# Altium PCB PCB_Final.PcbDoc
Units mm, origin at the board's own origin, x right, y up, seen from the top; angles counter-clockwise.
Board outline 33.1 x 39.88 mm, 2 copper layers (Top Layer, Bottom Layer); 74 components, 65 nets, 291 pads, 28 vias.
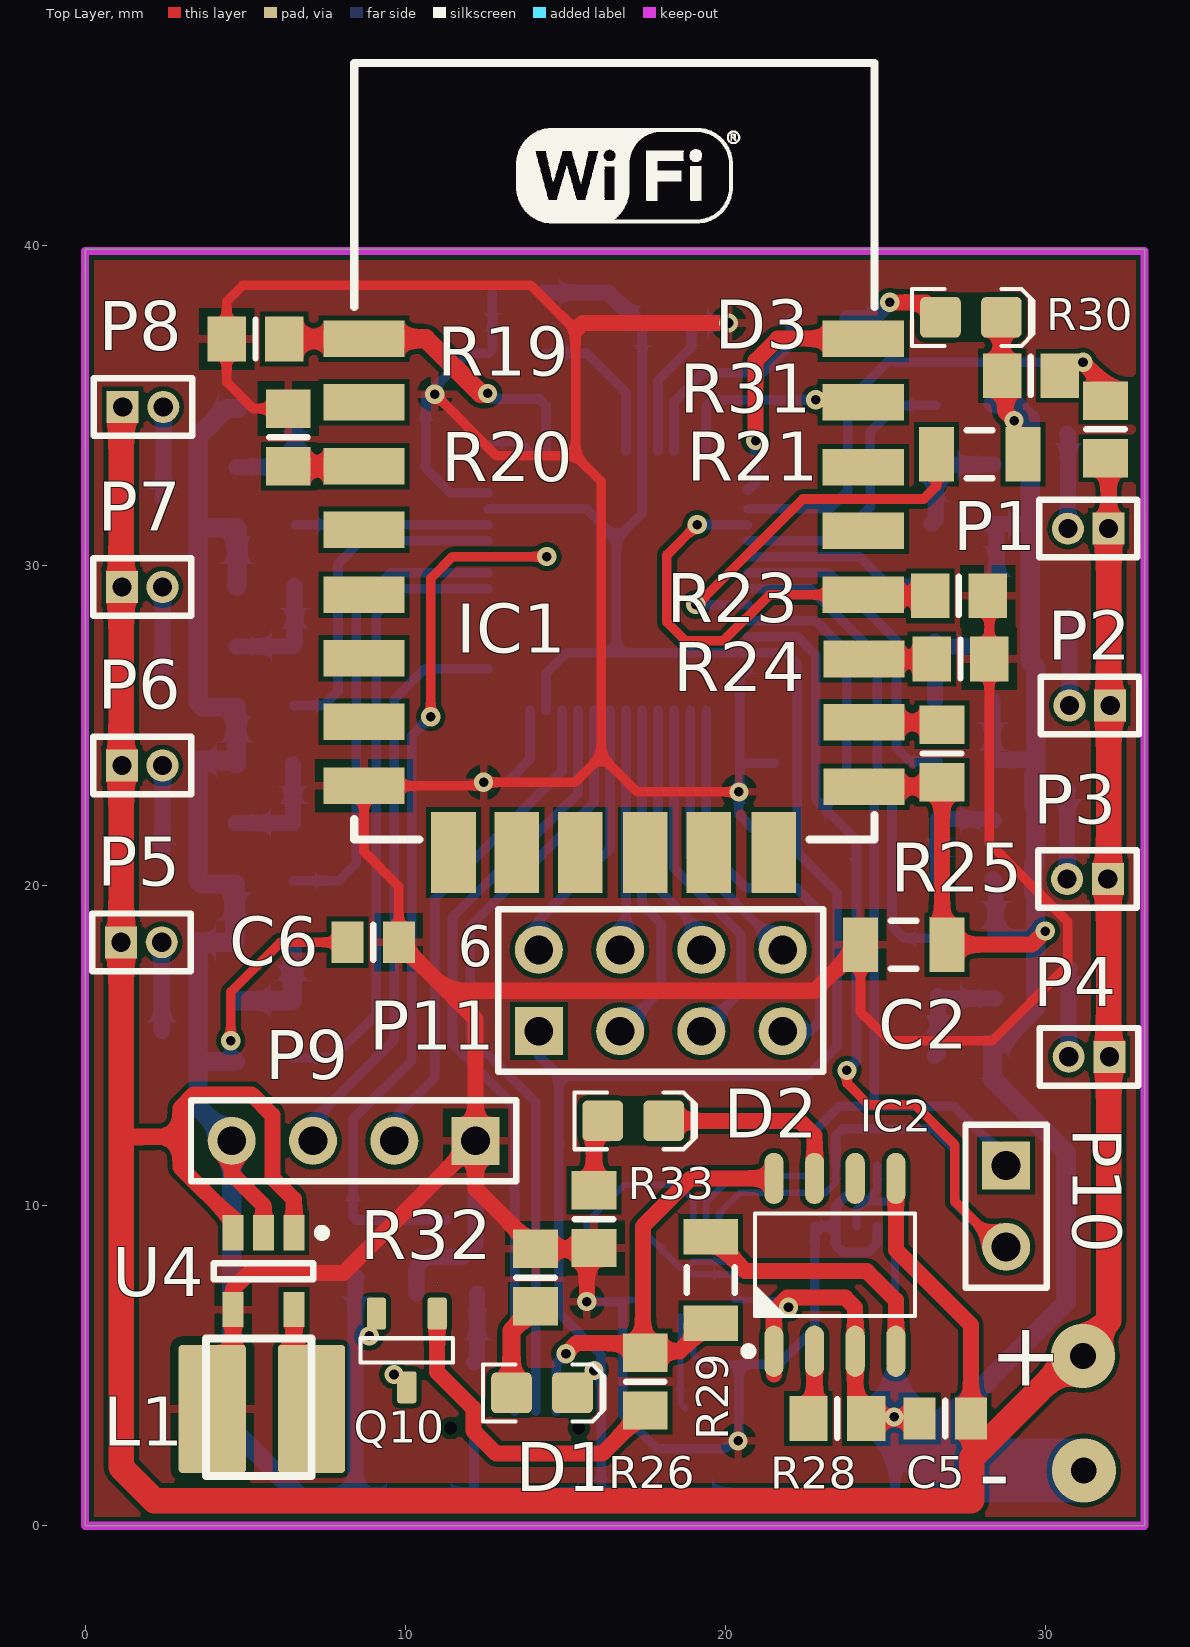
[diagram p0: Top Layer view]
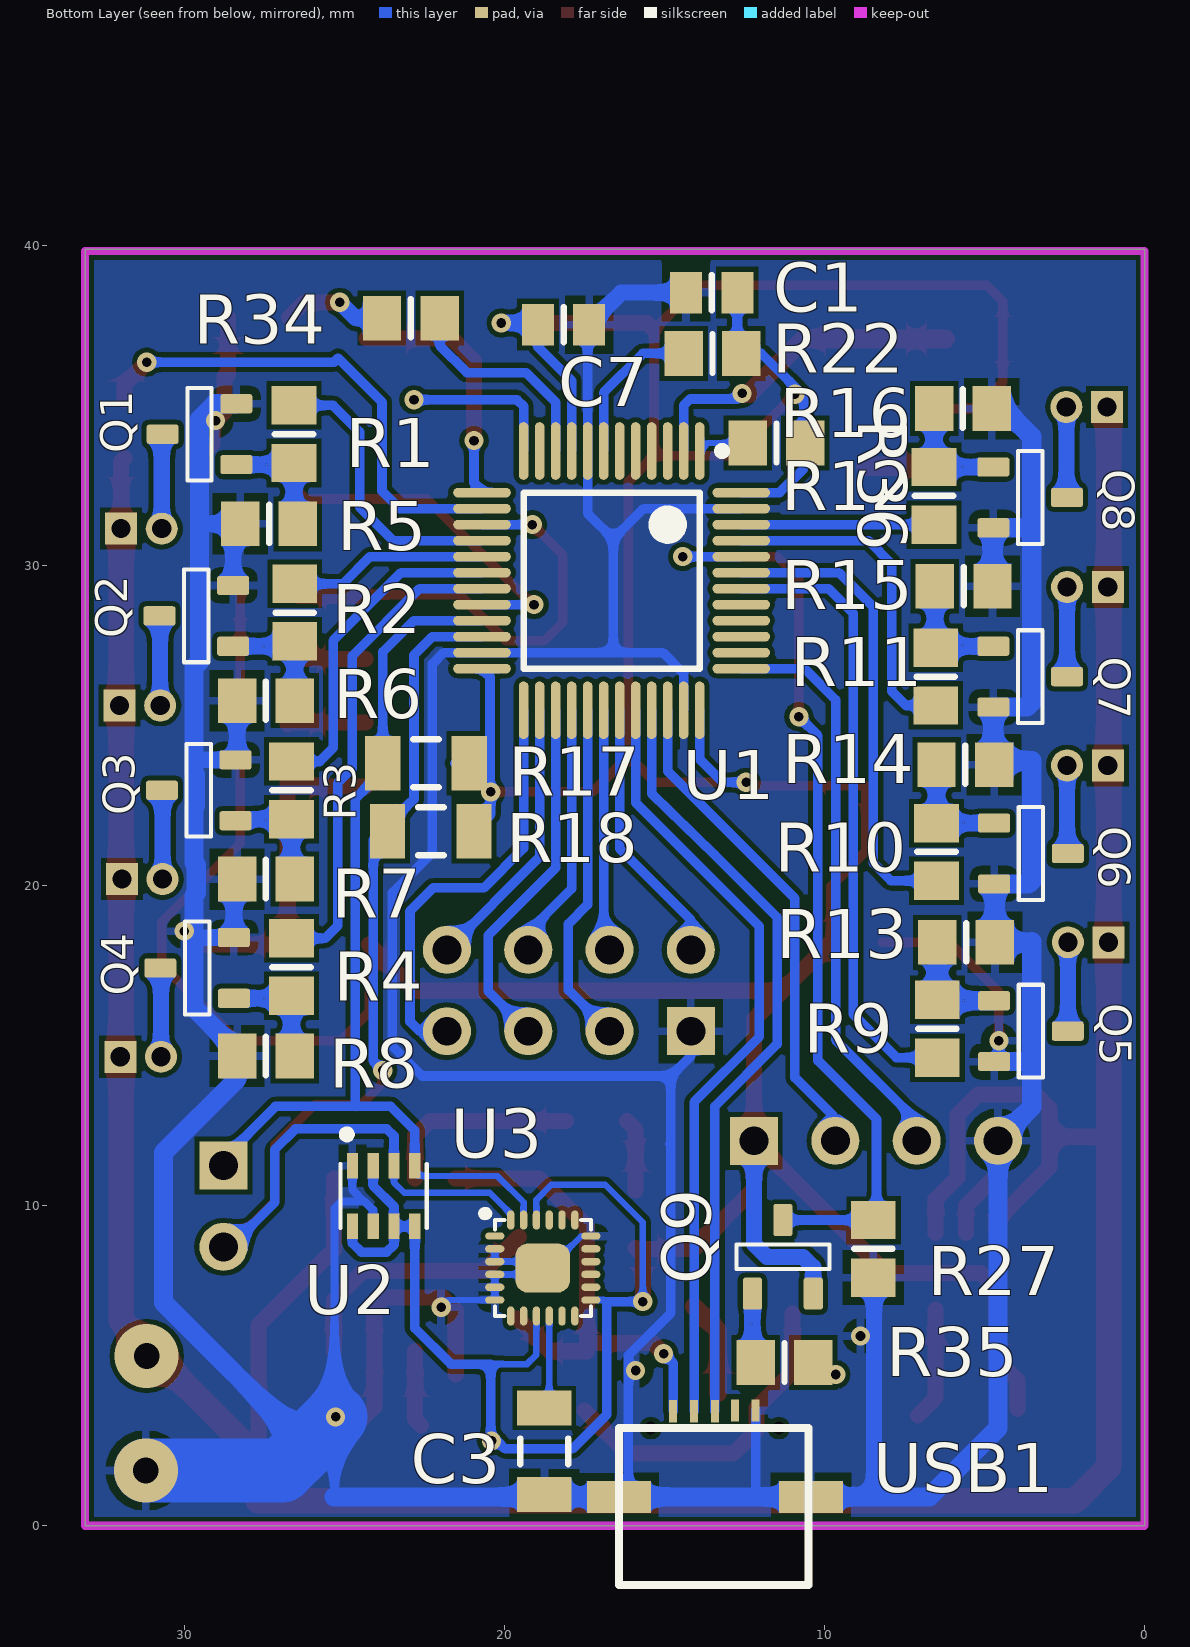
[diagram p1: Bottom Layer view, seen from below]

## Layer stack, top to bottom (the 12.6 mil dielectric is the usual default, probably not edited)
Top Solder: solder mask 0.0102, Solder Resist, Dk 3.5
Top Layer: signal copper 0.0356
Dielectric 1: dielectric 0.32, FR-4, Dk 4.8
Bottom Layer: signal copper 0.0356
Bottom Solder: solder mask 0.0102, Solder Resist, Dk 3.5

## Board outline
0,0 33.1,0 33.1,39.875 0,39.875

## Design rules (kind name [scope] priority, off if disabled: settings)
Clearance [All] p1: gap=0.15
PolygonConnect [All] p1: connectstyle=Relief reliefconductorwidth=0.254 reliefentries=4 polygonreliefangle="90 Angle" airgapwidth=0.254
RoutingVias [All] p1: holewidth=0.711 width=1.27 viastyle="Through Hole" minholewidth=0.711 minwidth=1.27 maxholewidth=0.711 maxwidth=1.27
SolderMaskExpansion [All] p1: expansion=0.102
Width [All] p1: maxlimit=2 minlimit=0.2 preferedwidth=0.5
30 further rules are at their usual default settings.

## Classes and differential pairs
component class Potencia: C5 C6 C7 C? D1 D2 D3 IC2 L1 P1 P2 P3 P4 P5 P6 P7 P8 P? Q1 Q2 Q3 Q4 Q5 Q6 Q7 Q8 Q? R1 R2 R3 R4 R5 R6 R7 R8 R9 R10 R11 R12 R13 R14 R15 R16 R28 R29 R32 R33 R34 R? U4
component class Esquematico: C1 C2 C3 C? IC1 P9 P10 P11 Q9 Q10 R17 R18 R19 R20 R21 R22 R23 R24 R25 R26 R27 R30 R31 R35 R36 R? U1 U2 U3 U? USB1

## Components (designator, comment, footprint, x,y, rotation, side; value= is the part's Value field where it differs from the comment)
C1 "Cap" 6-0805_L 13.525,38.525 r180 bottom
C2 "Cap" C1206 25.575,18.15 r180 top
C3 "Cap" C1206 18.75,2.325 r90 bottom
C5 "Cap" 6-0805_L 26.875,3.35 r0 top
C6 "Cap" 6-0805_L 9,18.225 r0 top
C7 "Cap" 6-0805_L 18.15,37.525 r0 bottom
D1 "Diode" LED-0805 14.275,4.15 r0 top
D2 "Diode" LED-0805 17.125,12.65 r0 top
D3 "Diode" LED-0805 27.675,37.75 r0 top
IC1 "ESP8266 ESP-12-E" "ESP8266 ESP-12-E B" 25.3,20.675 r0 top
IC2 "TP4056" SOIC127P600X175-8AN 23.425,8.15 r90 top
L1 "Inductor Iron Dot" "Inductor CD43" 8.075,1.65 r90 top
P1 "MHDR1X2" MHDR1X2 31.975,31.15 r180 top
P2 "MHDR1X2" MHDR1X2 32.025,25.625 r180 top
P3 "MHDR1X2" MHDR1X2 31.95,20.2 r180 top
P4 "MHDR1X2" MHDR1X2 32,14.65 r180 top
P5 "MHDR1X2" MHDR1X2 1.125,18.225 r0 top
P6 "MHDR1X2" MHDR1X2 1.15,23.75 r0 top
P7 "MHDR1X2" MHDR1X2 1.15,29.325 r0 top
P8 "MHDR1X2" MHDR1X2 1.175,34.95 r0 top
P9 "Header 4" HDR1X4 12.2,12.025 r180 top
P10 "Header 2" HDR1X2 28.775,11.25 r270 top
P11 "Header 4X2A" HDR2X4_CEN 14.175,15.45 r0 top
Q1 "AO3406" SOT23-3 29.525,34.1 r0 bottom
Q2 "AO3406" SOT23-3 29.625,28.425 r0 bottom
Q3 "AO3406" SOT23-3 29.55,22.975 r0 bottom
Q4 "AO3406" SOT23-3 29.6,17.425 r0 bottom
Q5 "AO3406" SOT23-3 3.55,15.45 r180 bottom
Q6 "AO3406" SOT23-3 3.55,21 r180 bottom
Q7 "AO3406" SOT23-3 3.575,26.525 r180 bottom
Q8 "AO3406" SOT23-3 3.575,32.125 r180 bottom
Q9 "S8055" SOT23-3 11.3,8.4 r90 bottom
Q10 "S8050" SOT23-3 10.05,5.475 r270 top
R1 "Res3" 6-0805_N 26.575,34.1 r90 bottom
R2 "Res3" 6-0805_N 26.55,28.525 r90 bottom
R3 "Res3" 6-0805_N 26.65,22.975 r90 bottom
R4 "Res3" 6-0805_N 26.65,17.45 r90 bottom
R5 "Res3" 6-0805_N 27.35,31.3 r180 bottom
R6 "Res3" 6-0805_N 27.45,25.775 r180 bottom
R7 "Res3" 6-0805_N 27.45,20.2 r180 bottom
R8 "Res3" 6-0805_N 27.45,14.675 r180 bottom
R9 "Res3" 6-0805_N 6.475,15.525 r270 bottom
R10 "Res3" 6-0805_N 6.5,21.05 r270 bottom
R11 "Res3" 6-0805_N 6.525,26.525 r270 bottom
R12 "Res3" 6-0805_N 6.575,32.175 r270 bottom
R13 "Res3" 6-0805_N 5.575,18.225 r0 bottom
R14 "Res3" 6-0805_N 5.6,23.775 r0 bottom
R15 "Res3" 6-0805_N 5.65,29.35 r0 bottom
R16 "Res3" 6-0805_N 5.675,34.9 r0 bottom
R17 "Res3" C1206 22.45,23.825 r0 bottom
R18 "Res3" C1206 22.3,21.7 r0 bottom
R19 "Res3" 6-0805_N 5.325,37.075 r180 top
R20 "Res3" 6-0805_N 6.35,34 r90 top
R21 "Res3" C1206 27.95,33.475 r0 top
R22 "Res3" 6-0805_N 13.5,36.625 r180 bottom
R23 "Res3" 6-0805_N 27.3,29.05 r0 top
R24 "Res3" 6-0805_N 27.35,27.075 r180 top
R25 "Res3" 6-0805_N 26.775,24.125 r90 top
R26 "Res3" 6-0805_N 17.5,4.5 r270 top
R27 "Res3" 6-0805_N 8.475,8.65 r270 bottom
R28 "Res3" 6-0805_N 23.5,3.35 r0 top
R29 "Res3" C1206 19.55,7.675 r90 top
R30 "Res3" 6-0805_N 31.875,34.25 r90 top
R31 "Res3" 6-0805_N 29.55,35.925 r180 top
R32 "Res3" 6-0805_N 14.075,7.75 r90 top
R33 "Res3" 6-0805_N 15.9,9.575 r270 top
R34 "Res3" 6-0805_N 22.925,37.725 r180 bottom
R35 "Res3" 6-0805_N 11.25,5.1 r180 bottom
R36 "Res3" 6-0805_N 11.5,33.825 r180 bottom
U1 "STM32F103C8T6" LQFP48_N 16.65,29.525 r270 bottom
U2 "BMP280" LGA-8_BMP280(Primary) 23.775,10.3 r90 bottom
U3 "GYRO/ACCEL/COMPASS/9-AXIS" QFN-24/3MM 18.8,8.05 r180 bottom
U4 "LM3671MF-3.3/NOPB" MF05A_N 5.575,7.95 r270 top
USB1 "Micro_USB" "Micro USB" 15.425,3.05 r180 bottom

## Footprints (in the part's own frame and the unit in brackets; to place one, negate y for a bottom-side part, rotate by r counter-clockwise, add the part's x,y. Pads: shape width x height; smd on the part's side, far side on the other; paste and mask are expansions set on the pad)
6-0805_L [mm] "Chip Resistor, Body 2.0x1.2mm, IPC High Density"
  rect 1x1.3 smd: 1(-0.8,0) 2(0.8,0)
  silkscreen extent 0,-0.55 0,0.55, body extent -1.07,-0.7 1.07,0.7, height 0.7
6-0805_N [mm] "Chip Resistor, Body 2.0x1.2mm, IPC Medium Density"
  rect 1.2x1.4 smd: 1(-0.9,0) 2(0.9,0)
  silkscreen extent 0,-0.6 0,0.6, body extent -1.07,-0.7 1.07,0.7, height 0.7
C1206 [mm] "Chip Capacitor, Body 3.2x1.6mm, IPC High Density"
  rect 1.1x1.7 smd: 1(-1.35,0) 2(1.35,0)
  silkscreen extent -0.4,-0.75 0.4,0.75, body extent -1.7,-0.9 1.7,0.9, height 1.3
"ESP8266 ESP-12-E B" [mil] "ESP8266 ESP-12-E"
  rect 100x45 smd: 1(-653,646) 2(-653,568) 3(-653,489) 4(-653,411) 5(-653,331) 6(-653,253) 7(-653,175) 8(-653,96) 15(-38,95) 16(-38,174) 17(-38,252) 18(-39,331) 19(-39,410) 20(-39,488) 21(-39,568) 22(-39,646)
  rect 55x100 smd: 9(-543,14) 10(-465,14) 11(-387,14) 12(-307,14) 13(-229,14) 14(-149,14)
  silkscreen extent -665,30 -25,985
HDR1X2 [mm] "Connector; Header; 2 Position"
  rect 1.5x1.5 hole 0.9: 1(0,0)
  round 1.5 hole 0.9: 2(2.54,0)
  silkscreen extent -1.27,-1.27 3.81,1.27
HDR1X4 [mm] "Connector; Header; 4 Position"
  rect 1.5x1.5 hole 0.9: 1(0,0)
  round 1.5 hole 0.9: 2(2.54,0) 3(5.08,0) 4(7.62,0)
  silkscreen extent -1.27,-1.27 8.89,1.27
HDR2X4_CEN [mm] "Connector; Header; 4x2 Position"
  rect 1.5x1.5 hole 0.9: 1(0,0)
  round 1.5 hole 0.9: 2(2.54,0) 3(5.08,0) 4(7.62,0) 5(0,2.54) 6(2.54,2.54) 7(5.08,2.54) 8(7.62,2.54)
  silkscreen extent -1.27,-1.27 8.89,3.81
"Inductor CD43" [mm] "4.5mm * 4mm"
  rrect10% 4x2.1 smd: 1(2,1) 2(2,4.1)
  silkscreen extent -0.1,1 4.2,4.3
LED-0805 [mil]
  round 20 on Mech15: 0(0,0)
  rrect25% 50x50 smd: 1(-37.5,0) 2(37.5,0)
  Top Layer pour cut-out: -15,30 15,30 15,-30 -15,-30
  silkscreen extent -72,-35 77,35, body extent -39,-25 39,25, height 31
LGA-8_BMP280(Primary) [mm]
  rect 0.8x0.35 smd paste-25.4 mask-25.4: 1(0.95,0.975) 2(0.95,0.325) 3(0.95,-0.325) 4(0.95,-0.975) 5(-0.95,-0.975) 6(-0.95,-0.325) 7(-0.95,0.325) 8(-0.95,0.975)
  silkscreen extent -1,-1.35 2.02,1.35
LQFP48_N [mm] "Thin QFP, 48-Leads, Body 7x7mm, Pitch 0.5mm, IPC Medium Density"
  oval 1.8x0.3 smd: 1(-4.05,2.75) 2(-4.05,2.25) 3(-4.05,1.75) 4(-4.05,1.25) 5(-4.05,0.75) 6(-4.05,0.25) 7(-4.05,-0.25) 8(-4.05,-0.75) 9(-4.05,-1.25) 10(-4.05,-1.75) 11(-4.05,-2.25) 12(-4.05,-2.75) 25(4.05,-2.75) 26(4.05,-2.25) 27(4.05,-1.75) 28(4.05,-1.25) 29(4.05,-0.75) 30(4.05,-0.25) 31(4.05,0.25) 32(4.05,0.75) 33(4.05,1.25) 34(4.05,1.75) 35(4.05,2.25) 36(4.05,2.75)
  oval 0.3x1.8 smd: 13(-2.75,-4.05) 14(-2.25,-4.05) 15(-1.75,-4.05) 16(-1.25,-4.05) 17(-0.75,-4.05) 18(-0.25,-4.05) 19(0.25,-4.05) 20(0.75,-4.05) 21(1.25,-4.05) 22(1.75,-4.05) 23(2.25,-4.05) 24(2.75,-4.05) 37(2.75,4.05) 38(2.25,4.05) 39(1.75,4.05) 40(1.25,4.05) 41(0.75,4.05) 42(0.25,4.05) 43(-0.25,4.05) 44(-0.75,4.05) 45(-1.25,4.05) 46(-1.75,4.05) 47(-2.25,4.05) 48(-2.75,4.05)
  silkscreen extent -4.17,-2.75 2.75,3.57, body extent -3.5,-3.5 3.5,3.5, height 1.6
MF05A_N [mm] "SOT23, 5-Leads, Body 2.9x1.6mm, Pitch 0.95mm, Lead Span 2.8mm, IPC Medium Density"
  rect 1.1x0.65 smd: 1(-1.2,0.95) 2(-1.2,0) 3(-1.2,-0.95) 4(1.2,-0.95) 5(1.2,0.95)
  silkscreen extent -1.32,-1.55 0.25,1.95, body extent -0.9,-1.55 0.9,1.55, height 1.19
MHDR1X2 [mm] "Connector; Header; 2 Position"
  rect 1x1 hole 0.6: 1(0,0)
  round 1 hole 0.6: 2(1.27,0)
  silkscreen extent -0.9,-0.9 2.17,0.9
"Micro USB" [mm]
  round 0 hole 0.4: 0(0,0) 0(4,0)
  rect 0.25x0.7 smd: 1(0.7,0.525) 2(1.35,0.525) 3(2,0.525) 4(2.625,0.55) 5(3.275,0.55)
  rect 2x1 smd: 6(-1,-2.15) 6(5,-2.15)
  silkscreen extent -1,-4.9 4.92,0
QFN-24/3MM [mm]
  rrect50% 1.7x1.54 smd: 0(0,0)
  rrect100% 0.6x0.23 smd: 1(-1.5,1) 2(-1.5,0.6) 3(-1.5,0.2) 4(-1.5,-0.2) 5(-1.5,-0.6) 6(-1.5,-1) 13(1.5,-1) 14(1.5,-0.6) 15(1.5,-0.2) 16(1.5,0.2) 17(1.5,0.6) 18(1.5,1)
  rrect100% 0.23x0.6 smd: 7(-1,-1.5) 8(-0.6,-1.5) 9(-0.2,-1.5) 10(0.2,-1.5) 11(0.6,-1.5) 12(1,-1.5) 19(1,1.5) 20(0.6,1.5) 21(0.2,1.5) 22(-0.2,1.5) 23(-0.6,1.5) 24(-1,1.5)
  silkscreen extent -2,-1.5 1.5,1.9
SOIC127P600X175-8AN [mm] "SOIC, 8-Leads, Body 4.9x3.9mm, Pitch 1.27mm, IPC Medium Density"
  round 1 on Mech15: 0(0,0)
  oval 1.6x0.6 smd: 1(-2.7,1.905) 2(-2.7,0.635) 3(-2.7,-0.635) 4(-2.7,-1.905) 5(2.7,-1.905) 6(2.7,-0.635) 7(2.7,0.635) 8(2.7,1.905)
  silkscreen extent -2.82,-2.5 1.6,2.82, body extent -3,-2.45 3,2.45, height 1.75
SOT23-3 [mm] "SOT23, 3 pin"
  round 0.5 on Mech15: 0(0,0)
  rrect25% 1x0.6 smd: 1(-1.15,0.95) 2(-1.15,-0.95) 3(1.15,0)
  silkscreen extent -0.38,-1.45 0.38,1.45, body extent -1.4,-1.45 1.4,1.45, height 1.29

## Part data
C1 C2 C3 C5 C6 C7: "Capacitor"
D1 D2 D3: "Default Diode"
L1: "Magnetic-Core Inductor with Winding Polarity Marking"
P1 P2 P3 P4 P5 P6 P7 P8 P10: "Header, 2-Pin"
P9: "Header, 4-Pin"
P11: "Header, 4-Pin, Dual row"
Q1 Q2 Q3 Q4 Q5 Q6 Q7 Q8: library part MOSFET-N, "N-Channel MOSFET"
Q9: "PNP SMD General Purpose Amplifier"
Q10: "NPN SMD General Purpose Amplifier"
R1 R2 R3 R4 R5 R6 R7 R8 R9 R10 R11 R12 R13 R14 R15 R16 R17 R18 R19 R20 R21 R22 R23 R24 R25 R26 R27 R28 R29 R30 R31 R32 R33 R34 R35 R36: "Resistor"
U1: "STM32 ARM-based 32-bit MCU with 64 Kbytes Flash, 48-pin LQFP, Industrial Temperature"
U2: "Barometro"
U3: library part MPU-9250
U4: "2MHz, 600mA Step-Down DC-DC Converter, 5-pin SOT-23, Pb-Free"

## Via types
v1: diameter 0.6, hole 0.3, Top Layer to Bottom Layer, 25 vias
v2: diameter 2, hole 0.8, Top Layer to Bottom Layer, 2 vias
v3: diameter 0.6, hole 0.3, Top Layer to Bottom Layer, tented both sides, 1 vias

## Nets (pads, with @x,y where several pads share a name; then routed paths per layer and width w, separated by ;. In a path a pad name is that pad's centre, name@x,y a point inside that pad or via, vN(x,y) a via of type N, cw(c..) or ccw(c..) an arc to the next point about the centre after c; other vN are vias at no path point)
ADC: R30.2 R31.1 U1.14 | length 15.6
  Top Layer w0.5: v1(31.175,36.35) 31.875,35.65 R30.2
  Bottom Layer w0.3: U1.14 23.275,31.775 23.825,32.325 23.825,35.1 25.2,36.475 25.325,36.35 v1(31.175,36.35)
BOOT_0: Q9.3 R27.1 U1.44 | length 29.7
  Top Layer w0.3: v1(10.8,25.275) 10.8,29.6 11.475,30.275 v1(14.425,30.275)
  Bottom Layer w0.3: v1(10.8,25.275) 10.208,24.683 10.208,14.533 8.375,12.7 8.375,9.65 R27.1 Q9.3 ; U1.44 v1(14.425,30.275)
BOOT_ESP: IC1.18 R23.1 U1.15 | length 14.1
  Top Layer w0.3: v1(19.125,31.275) 18.175,30.325 18.175,28.225 18.75,27.65 19.95,27.65 21.382,29.082 IC1.18
  Top Layer w0.5: IC1.18 24.342,29.05 R23.1
  Bottom Layer w0.3: v1@19.1,31.25 v1(19.125,31.275) U1.15
CHARGE: D2.2 IC2.7 | length 6.2
  Top Layer w0.5: D2.2 22.325,12.65 22.79,12.185 IC2.7
GND: C1.1 C2.1 C3.1 C5.1 C6.1 C7.1 D1.2 D3.2 IC1.15 IC2.1 IC2.3 P9.4 P11.1 Q1.2 Q2.2 Q3.2 Q4.2 Q5.2 Q6.2 Q7.2 Q8.2 Q10.2 R5.1 R6.1 R7.1 R8.1 R13.1 R14.1 R15.1 R16.1 R21.2 R25.1 R27.2 R28.2 R31.2 U1.8 U1.23 U1.35 U1.47 U2.1 U2.7 U3.0 U3.2 U3.3 U3.4 U3.5 U3.6 U3.18 U4.2 USB1.5 USB1.6 | length 247.1
  Top Layer w0.3: v1(4.55,15.15) 4.55,16.675 6.1,18.225 C6.1 ; v1(29.025,34.525) 29.025,33.75 R21.2
  Top Layer w0.5: P9.4 4.58,10.995 5.575,10 U4.2 ; IC2.1@21.52,4.72 IC2.1 21.52,6.72 21.925,7.125 23.75,7.125 24.06,6.815 IC2.3 24.06,3.715 24.425,3.35 C5.1 ; IC1.15 26.638,23.088 R25.1 26.775,18.3 C2.1 29.575,18.15 v1(30,18.575) ; D3.2 28.627,35.947 R31.2 ; R31.2@28.75,35.925 28.75,34.8 v1(29.025,34.525)
  Bottom Layer w0.2: U3.18 17.599,9.05 17.634,9.015 ; 17.651,9 18.601,8.05 U3.0 ; U3.2 U3.3 19,8.25 U3.0 ; v1(21.975,6.825) 21.75,7.05 U3.6 U3.5 U3.4 19,7.85 U3.0
  Bottom Layer w0.256: 14.8,9.325 14.825,9.3 ; 14.8,11.975 14.85,11.925 ; U2.7 24.1,9.868 24.364,10.132 24.395,10.132 ; U2.1 24.75,10.487 24.395,10.132 ; 25.325,0.9 25.307,0.918 25.307,3.368 25.307,9.908 25.083,10.132 24.395,10.132
  Bottom Layer w0.3: v1(4.55,15.15) 4.55,14.65 Q5.2 ; USB1.5 12.15,0.925 12.175,0.9 ; U1.47 15.65,31.775 16.6,30.825 ; P11.1 14.175,14.675 14.8,14.05 ; U1.35 14.4,26.625 15.05,27.275 16.6,27.275 ; USB1.6@16.425,0.9 16.125,1.2 16.125,5.325 14.8,6.65 14.8,9.325 14.8,11.975 14.8,14.05 ; C7.1 17.4,37.475 U1.8 17.4,31.625 16.6,30.825 ; 14.8,14.05 22.567,14.05 23.504,14.987 23.504,19.775 22.25,21.029 22.25,26.925 21.9,27.275 U1.23 16.6,27.275 ; 16.6,27.275 16.6,30.825
  Bottom Layer w0.5: 8.45,0.9 8.45,7.725 R27.2 ; C1.1 16.35,38.525 C7.1 ; R7.1 28.45,20.1 Q4.2 29.625,18.375 ; R6.1 28.35,23.975 Q3.2 29.675,23.925 29.7,23.95 ; Q2.2 28.475,31.075 R5.1 29.429,31.3 29.529,31.2
  Bottom Layer w0.6: Q5.2 3.55,14.5 3.525,14.525 ; R15.1 4.75,31.15 Q8.2 3.6,31.175 3.525,31.25 ; R16.1 4.4,34.9 3.525,34.025 3.525,31.25 ; 9.1,0.925 9.075,0.9 ; 25.325,0.9 16.425,0.9 12.175,0.9 10.425,0.9 9.075,0.9 ; 26.176,2.499 30.65,6.973 30.65,11.658 28.35,13.958 R8.1 28.35,15.025 28.54,15.025 29.7,16.185 29.7,16.935 29.696,16.939 29.696,17.911 29.7,17.915 29.7,19.689 29.626,19.763 29.626,20.637 29.7,20.711 29.7,22.435 29.646,22.489 29.646,23.461 29.7,23.515 29.7,23.95 29.7,26.818 29.529,26.989 29.529,31.2 29.529,34.571 29.05,35.05 Q1.2 ; 3.525,14.525 3.525,13.08 P9.4 4.58,3.045 6.725,0.9 8.45,0.9 9.075,0.9 ; 3.525,14.525 3.525,18.25 3.55,18.225 R13.1 4.675,20.025 Q6.2 3.625,20.05 3.525,20.15 3.525,23.9 4.625,23.9 4.725,23.8 Q7.2 3.675,25.575 3.525,25.725 3.525,31.25
  Bottom Layer w2: v1(25.275,3.4) 25.307,3.368 26.176,2.499 26.95,1.725 v2(31.2,1.725)
  other v1: 15.9,4.85 8.875,5.925
GPIO0: P11.4 U1.25 | length 13.4
  Bottom Layer w0.3: U1.25 19.4,22.75 19.4,21.168 20.643,19.925 22.225,19.925 22.95,19.2 22.95,15.75 22.65,15.45 P11.4
GPIO1: P11.8 U1.26 | length 8.7
  Bottom Layer w0.3: U1.26 18.9,20.885 P11.8
GPIO2: P11.3 U1.27 | length 11.4
  Bottom Layer w0.3: U1.27 18.4,20.55 20.5,18.45 20.5,16.695 P11.3
GPIO3: P11.7 U1.28 | length 8
  Bottom Layer w0.3: U1.28 17.9,19.9 19.255,18.545 P11.7
GPIO4: P11.2 U1.29 | length 10.8
  Bottom Layer w0.3: P11.2 18,16.735 18,18.804 17.4,19.404 17.4,20.475 U1.29
GPIO5: P11.6 U1.30 | length 7.6
  Bottom Layer w0.3: P11.6 16.9,18.175 U1.30
GPIO6: P11.5 U1.31 | length 8.4
  Bottom Layer w0.3: P11.5 14.175,18.925 16.4,21.15 U1.31
"MOTOR 0": P1.2 Q1.3 | length 3
  Bottom Layer w0.5: Q1.3 30.705,34.07 P1.2
"MOTOR 1": P2.2 Q2.3 | length 2.8
  Bottom Layer w0.5: P2.2 30.755,28.405 Q2.3
"MOTOR 2": P3.2 Q3.3 | length 2.8
  Bottom Layer w0.5: P3.2 30.68,22.955 Q3.3
"MOTOR 3": P4.2 Q4.3 | length 2.8
  Bottom Layer w0.5: P4.2 30.73,17.405 Q4.3
"MOTOR 4": P5.2 Q5.3 | length 2.8
  Bottom Layer w0.5: P5.2 2.395,15.455 Q5.3
"MOTOR 5": P6.2 Q6.3 | length 2.8
  Bottom Layer w0.5: Q6.3 2.42,21.02 P6.2
"MOTOR 6": P7.2 Q7.3 | length 2.8
  Bottom Layer w0.5: P7.2 2.42,26.53 Q7.3
"MOTOR 7": P8.2 Q8.3 | length 2.8
  Bottom Layer w0.5: Q8.3 2.445,32.145 P8.2
NetC3_2: C3.2 U3.10 | length 2.9
  Bottom Layer w0.2: U3.10 18.6,3.825 C3.2
NetD1_1: D1.1 R32.1 | length 3
  Top Layer w0.56: D1.1 13.323,6.098 R32.1
NetD2_1: D2.1 R33.1 | length 2.3
  Top Layer w0.5: R33.1 15.9,12.378 D2.1
NetD3_1: D3.1 R34.1 | length 3.3
  Top Layer w0.5: v1(25.141,38.222) 26.251,38.222 D3.1
  Bottom Layer w0.5: R34.1 24.644,37.725 v1(25.141,38.222)
NetIC1_3: IC1.3 R20.1 | length 2.4
  Top Layer w0.6: R20.1 8.709,33.1 IC1.3
NetIC1_16: IC1.16 R25.2 | length 2.5
  Top Layer w0.5: IC1.16 26.705,25.095 R25.2
NetIC1_17: IC1.17 R24.2 | length 2.1
  Top Layer w0.5: IC1.17 R24.2@26.449,27.076
NetIC2_2: IC2.2 R28.1 | length 2.4
  Top Layer w0.5: R28.1@22.6,3.125 22.79,3.315 IC2.2
NetIC2_4: IC2.4 R29.2 | length 8.2
  Top Layer w0.5: R29.2 20.625,7.95 24.425,7.95 25.33,7.045 IC2.4
NetL1_1: L1.1 U4.5 | length 3.5
  Top Layer w0.5: U4.5 6.525,4 L1.1@7.075,3.45
NetQ1_2: Q1.1 R1.1 R5.2 | length 3.8
  Bottom Layer w0.5: R5.2 26.575,31.425 R1.1 26.625,33.15 Q1.1
NetQ2_2: Q2.1 R2.1 R6.2 | length 3.8
  Bottom Layer w0.5: R6.2 R2.1 26.7,27.475 Q2.1
NetQ3_2: Q3.1 R3.1 R7.2 | length 3.7
  Bottom Layer w0.5: R7.2 26.65,20.3 R3.1 28.35,22.075 Q3.1
NetQ4_2: Q4.1 R4.1 R8.2 | length 3.7
  Bottom Layer w0.5: R8.2 26.65,14.775 R4.1 26.725,16.475 Q4.1
NetQ5_2: Q5.1 R9.1 R13.2 | length 3.6
  Bottom Layer w0.6: Q5.1 6.45,16.4 R9.1 R13.2
NetQ6_2: Q6.1 R10.1 R14.2 | length 3.6
  Bottom Layer w0.5: Q6.1 R10.1 R14.2
NetQ7_2: Q7.1 R11.1 R15.2 | length 3.7
  Bottom Layer w0.5: Q7.1 6.475,27.475 6.55,27.55 R15.2
NetQ8_2: Q8.1 R12.1 R16.2 | length 3.7
  Bottom Layer w0.5: Q8.1 R12.1 R16.2
NetQ9_1: Q9.1 R35.1 | length 2.2
  Bottom Layer w0.5: R35.1 12.25,5.2 Q9.1
NetQ10_1: Q10.1 R26.2 | length 10.4
  Top Layer w0.5: Q10.1 11,4.8 12.129,3.671 12.129,2.971 12.85,2.25 16.15,2.25 R26.2
NetQ10_3: Q10.3 R35.2
  other v1: 9.65,4.725
NetR21_1: R21.1 U1.20 | length 11.7
  Top Layer w0.3: v1(19.075,28.775) 19.125,28.775 22.425,32.075 26.2,32.075 26.6,32.475 R21.1
  Bottom Layer w0.3: v1(19.075,28.775) U1.20
NetR36_1: R36.1 U1.1 | length 1.6
  Bottom Layer w0.2: R36.1 13.65,33.825 U1.1
NRST: R22.1 U1.7 | length 4.8
  Bottom Layer w0.3: R22.1 15.675,36.625 16.9,35.4 U1.7
PWM0: R1.2 U1.16 | length 9
  Bottom Layer w0.3: U1.16 23.475,30.775 24.525,31.825 24.525,34.175 25.35,35 R1.2
PWM1: R2.2 U1.17 | length 6.2
  Bottom Layer w0.3: U1.17 24.2,30.275 25.05,29.425 R2.2
PWM2: R3.2 U1.18 | length 10.4
  Bottom Layer w0.3: U1.18 23.225,29.775 25.35,27.65 25.35,24.3 25.775,23.875 R3.2
PWM3: R4.2 U1.19 | length 15.1
  Bottom Layer w0.3: U1.19 22.65,29.275 24.754,27.171 24.754,23.654 25.208,23.2 25.208,18.742 25.6,18.35 R4.2
PWM4: R9.2 U1.42 | length 19.5
  Bottom Layer w0.3: R9.2 7.75,14.625 9.1,15.975 9.1,28.5 9.875,29.275 U1.42
PWM5: R10.2 U1.43 | length 14.8
  Bottom Layer w0.3: R10.2 7.925,20.15 8.475,20.7 8.475,28.7 9.55,29.775 U1.43
PWM6: R11.2 U1.45 | length 10.5
  Bottom Layer w0.3: R11.2 7.45,25.625 7.9,26.075 7.9,30.05 8.625,30.775 U1.45
PWM7: R12.2 U1.46 | length 6
  Bottom Layer w0.3: R12.2 U1.46
RST: IC1.1 R19.1 U1.2 | length 10.5
  Top Layer w0.6: R19.1 8.705,37.075 IC1.1 10.642,37.083 12.35,35.375 v1(12.575,35.375)
  Bottom Layer w0.3: v1(12.575,35.375) 12.575,35.35 12.725,35.2 14.2,35.2 14.4,35 U1.2
RX: IC1.22 U1.13 | length 7.8
  Top Layer w0.5: v3(20.95,33.9) 20.95,36.4 21.633,37.083 IC1.22
  Bottom Layer w0.3: U1.13@20.7,32.329 20.95,32.579 v3(20.95,33.9)
SCL: P10.1 R17.2 U1.21 U2.4 U3.23 | length 30.9
  Bottom Layer w0.2: U3.23 19.4,10.1 20.225,10.925 22.7,10.925 22.8,11.025 U2.4
  Bottom Layer w0.3: U1.21 22.825,28.275 23.8,27.3 R17.2 23.8,23.575 24.654,22.721 24.654,13.104 24.65,13.1 ; U2.4 22.8,12.35 23.55,13.1 24.65,13.1 ; P10.1@28.9,11.35 27.15,13.1 24.65,13.1
SDA: P10.2 R18.2 U1.22 U2.3 U3.24 | length 38.1
  Top Layer w0.3: v1(23.8,14.225) 23.8,13.825 24.475,13.15 25.925,13.15 27.175,11.9 27.175,10.125 28.59,8.71 P10.2
  Bottom Layer w0.2: U3.24 19.8,9.742 20.458,10.4 23.131,10.4 23.45,10.719 U2.3
  Bottom Layer w0.3: U1.22 22.25,27.775 22.825,27.2 22.825,22.7 24.1,21.425 24.1,14.525 v1(23.8,14.225) ; U2.3 23.45,12.175 23.675,12.4 26.525,12.4 27.175,11.75 27.175,10.1 28.565,8.71 P10.2
STATE: R34.2 U1.10 | length 6.7
  Bottom Layer w0.3: U1.10 18.4,35.1 19.325,36.025 21.175,36.025 22.025,36.875 R34.2
SWCLK: P9.3 U1.37 | length 18.3
  Bottom Layer w0.3: P9.3@7.195,11.825 7.195,12.72 9.654,15.179 9.654,25.804 10.625,26.775 U1.37
SWDIO: P9.2 U1.34 | length 15.8
  Bottom Layer w0.3: P9.2@9.735,11.825 9.735,12.81 10.925,14 10.925,19.6 14.9,23.575 U1.34
TX: IC1.21 U1.12 | length 4.9
  Bottom Layer w0.3: U1.12 19.4,34.975 19.6,35.175 v1(22.825,35.175)
  other v1: 22.825,35.175
USB_DM: U1.32 USB1.2 | length 24.3
  Bottom Layer w0.3: USB1.2 14.075,5.721 14.075,13.233 12.033,15.275 12.033,18.722 15.9,22.589 U1.32
USB_DP: U1.33 USB1.3 | length 24.4
  Bottom Layer w0.3: USB1.3 13.429,3.575 13.429,13.096 11.479,15.046 11.479,19.008 13.429,20.958 15.4,22.875 U1.33
VCC: C1.2 C2.2 C6.2 C7.2 IC1.8 L1.2 P9.1 Q9.2 R17.1 R18.1 R19.2 R20.2 R22.2 R23.2 R24.1 R32.2 R33.2 R36.2 U1.9 U1.24 U1.36 U1.48 U2.2 U2.5 U2.6 U2.8 U3.9 U3.13 U3.22 U4.4 | length 186
  Top Layer w0.3: R20.2 5.25,34.9 4.425,35.725 R19.2 4.425,38.25 4.925,38.75 13.925,38.75 15.325,37.35 15.325,33.425 ; C6.2 9.8,19.975 8.714,21.061 IC1.8 12.338,23.113 v1(12.45,23.225) 15.3,23.225 16.125,24.05 ; v1(10.925,35.35) 12.85,33.425 15.325,33.425 ; v1(20.425,22.925) 17.25,22.925 16.125,24.05 ; C2.2 24.225,16.05 25.125,15.15 28.341,15.15 30.704,17.513 30.704,18.867 28.25,21.321 R24.1 28.25,29 R23.2 ; 15.325,33.425 16.125,32.625 16.125,24.05
  Top Layer w0.5: L1.2 3.975,4.55 4.625,5.2 U4.4 4.625,7.4 5.125,7.9 8.075,7.9 P9.1 ; C6.2 11.312,16.713 ; 15.325,37.35 15.55,37.575 v1(20.1,37.575) ; v1(15.675,7) 15.675,8.45 R33.2@15.875,8.65 ; R33.2 R33.2@15.875,8.65 ; C2.2 22.788,16.713 11.312,16.713 ; 11.312,16.713 12.2,15.825 P9.1 ; P9.1 12.2,10.525 R32.2 R33.2@15.875,8.65
  Bottom Layer w0.2: v1(15.675,7) 15.675,9.475 16.85,10.65 18.534,10.65 19,10.184 U3.22 ; 16.8,7 16.85,7.05 U3.13 ; U3.9 19,5.343 19.292,5.05 20.425,5.05
  Bottom Layer w0.3: v1(12.45,23.225) 13.175,23.225 13.9,23.95 U1.36 ; U1.48 11.4,32.275 10.644,33.031 10.644,35.294 11.975,36.625 R22.2 12.725,36.75 C1.2 ; v1(15.675,7) 16.8,7 16.8,3.475 17.875,2.4 19.975,2.4 20.425,2.85 20.425,5.05 21.675,5.05 22.8,6.175 U2.5 U2.6 ; U1.9 17.9,35.775 18.95,36.825 C7.2 ; U1.24 20.45,26.525 20.45,23.9 ; R18.1 20.425,22.225 v1(20.425,22.925) 20.45,22.95 20.45,23.9 ; R17.1@21.55,23.825 20.525,23.825 20.45,23.9 ; U2.2 24.1,10.62 23.45,9.97 U2.6 ; U2.8 24.75,8.825 24.471,8.546 23.679,8.546 23.45,8.775 U2.6
  Bottom Layer w0.5: Q9.2 10.35,8.075 10.675,8.4 11.8,8.4 12.2,8.8 P9.1 ; C7.2 19,37.575 v1(20.1,37.575)
  other v1: 20.4,2.65
VCC_BAT: C5.2 IC2.5 P1.1 P2.1 P3.1 P4.1 P5.1 P6.1 P7.1 P8.1 R30.1 U4.1 U4.3 | length 119.3
  Top Layer w0.5: 1.125,12.225 1.125,12.15 2.975,12.15 ; U4.3 4.625,9.55 2.975,11.2 2.975,12.15 ; U4.1 6.525,10.2 5.85,10.875 5.85,12.825 5.2,13.475 3.4,13.475 2.975,13.05 2.975,12.15 ; IC2.5 25.33,8.62 27.675,6.275 C5.2 27.675,0.821 27.7,0.796 ; R30.1 31.975,33.25 P1.1
  Top Layer w0.8: 1.125,12.15 1.125,1.825 2.168,0.782 27.686,0.782 27.7,0.796 27.7,2.125 31.975,6.4 P1.1 ; 1.125,12.225 P5.1 1.125,34.9 P8.1
  other v2: 31.175,5.3
VCC_USB: IC2.8 R26.1 R29.1 USB1.1 | length 15.4
  Top Layer w0.5: v1(15.025,5.375) 15.35,5.7 17.425,5.7 17.425,9.35 18.925,10.85 IC2.8 ; R26.1@17.425,5.45 18.575,5.45 R29.1@19.6,6.475
  Bottom Layer w0.3: USB1.1 14.725,5.075 v1(15.025,5.375)
pads on no net: D1.0 D2.0 D3.0 IC1.2 IC1.4 IC1.5 IC1.6 IC1.7 IC1.9 IC1.10 IC1.11 IC1.12 IC1.13 IC1.14 IC1.19 IC1.20 IC2.0 IC2.6 Q1.0 Q2.0 Q3.0 Q4.0 Q5.0 Q6.0 Q7.0 Q8.0 Q9.0 Q10.0 U1.3 U1.4 U1.5 U1.6 U1.11 U1.38 U1.39 U1.40 U1.41 U3.1 U3.7 U3.8 U3.11 U3.12 U3.14 U3.15 U3.16 U3.17 U3.19 U3.20 U3.21 USB1.0 USB1.4

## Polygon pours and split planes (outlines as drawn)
VCC on Top Layer "PLANO_3V3" (solid, pour order 6): 0,0 33.1,0 33.1,39.825 0,39.825
GND on Bottom Layer "PLANO_GND" (solid, pour order 8): 0,39.825 33.1,39.825 33.1,0 0,0

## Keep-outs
Keep-Out Layer:
  lines w0.256: 0,0 0,39.825 33.1,39.825 33.1,0 0,0

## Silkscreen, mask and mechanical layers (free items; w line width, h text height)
Top Overlay:
  text "+" at 28.25,4.375 h2
  text "-" at 27.925,0.675 h2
